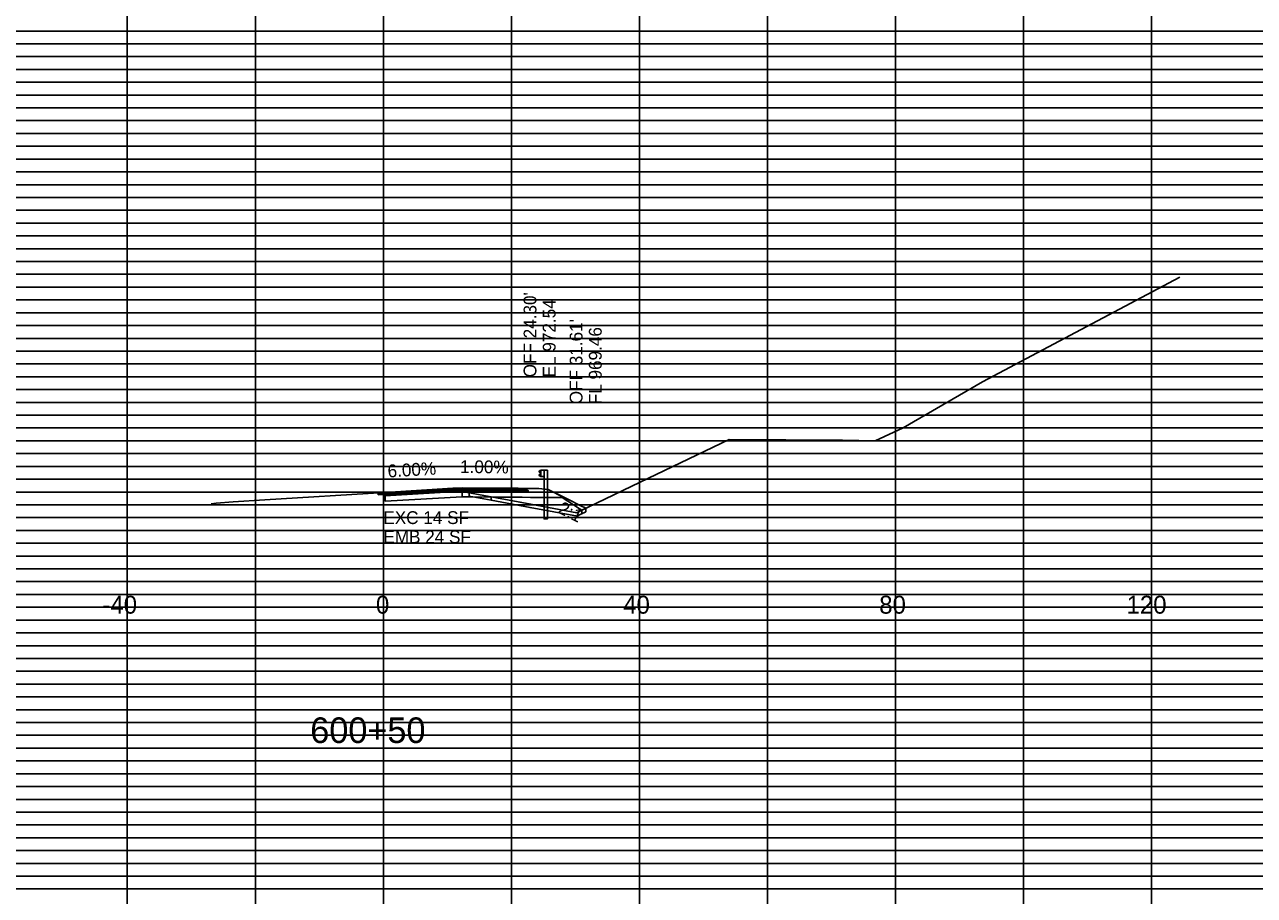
# Model space of a CAD drawing. Extents: x 2313580 to 2322968, y 282099 to 303247.
# Drawn here: x 2317145.2 to 2317337.4, y 287716.7 to 287852.7 of the extents above; entities that cross this region are included whole.
import ezdxf

# ---------------------------------------------------------------- set-up
doc = ezdxf.new("R2010")
doc.units = 0
for name, color, linetype in [('DESIGN - CENTERLINE - Proposed', 7, 'Continuous'), ('DESIGN - DRAINAGE - Text', 7, 'Continuous'), ('DESIGN - EARTHWORK - Excavation Limit Lines', 7, 'Continuous'), ('DESIGN - EARTHWORK - Shapes', 7, 'Continuous'), ('DESIGN - SCRATCH - User 5', 7, 'Continuous'), ('DESIGN - SHEET - Light Grid', 7, 'Continuous'), ('DESIGN - SHEET - Linework', 7, 'Continuous'), ('DESIGN - TYPICAL - Finished Grade and Subgrade', 7, 'Continuous'), ('DESIGN - TYPICAL - Finished Grade Slopes Text', 7, 'Continuous'), ('DESIGN - TYPICAL - Guardrail', 7, 'Continuous'), ('DESIGN - TYPICAL - Text', 7, 'Continuous'), ('Scratch Level', 7, 'Continuous'), ('SURVEY - GROUND - Top of Ground', 7, 'Continuous')]:
    doc.layers.add(name, color=color, linetype=linetype)

# ---------------------------------------------------------------- blocks, each defined once
blk = doc.blocks.new('GRTYP')
at = {"layer": 'DESIGN - CENTERLINE - Proposed'}
for p, q in [((0.162, 0.37), (0.162, 0.37)), ((0.162, 0.37), (0.162, 0.37)), ((0.264, 0.37), (0.264, 0.37)), ((0.264, 0.37), (0.264, 0.37))]:
    blk.add_line(p, q, dxfattribs=at)
for points in [[(0.059, 0.567), (0.04, 0.563), (0.004, 0.539), (0, 0.531), (0.004, 0.523), (0.055, 0.492), (0.059, 0.484), (0.059, 0.464), (0.055, 0.456), (0.004, 0.425), (0, 0.417), (0.004, 0.409), (0.04, 0.385), (0.059, 0.382)], [(0.162, 0.374), (0.059, 0.374), (0.059, 0.574), (0.162, 0.574)], [(0.264, -0.126), (0.264, 0.574), (0.162, 0.574), (0.162, -0.075)], [(0.162, -0.075), (0.162, -0.949), (0.264, -0.949), (0.264, -0.122)]]:
    blk.add_lwpolyline(points, dxfattribs=at)

msp = doc.modelspace()

# ---------------------------------------------------------------- linework, layer by layer
at = {"layer": 'DESIGN - EARTHWORK - Shapes'}
for points in [[(2317215.25, 287778.93), (2317214.68, 287779.03), (2317214.68, 287779.54), (2317213.6, 287779.74), (2317208.33, 287779.68), (2317201.47, 287779.61), (2317200.47, 287779.55), (2317200.47, 287779.45), (2317200.47, 287779.24), (2317201.58, 287779.3), (2317201.58, 287779.05), (2317201.58, 287778.22), (2317213.58, 287778.94)], [(2317218.13, 287778.9), (2317224.3, 287777.75), (2317231.5, 287776.44), (2317231.55, 287776.49), (2317231.79, 287776.6), (2317232.89, 287777.13), (2317232.05, 287777.55), (2317230.18, 287778.48), (2317229.58, 287778.78)]]:
    msp.add_lwpolyline(points, close=True, dxfattribs=at)
at = {"layer": 'DESIGN - SCRATCH - User 5'}
for points in [[(2317218.13, 287778.9), (2317214.68, 287779.54), (2317214.68, 287779.03), (2317218.13, 287778.39)], [(2317218.13, 287778.9), (2317214.68, 287779.54), (2317214.68, 287779.03), (2317218.13, 287778.39)], [(2317218.13, 287778.39), (2317224.21, 287777.25), (2317231.63, 287775.91), (2317231.82, 287776.06), (2317232.01, 287776.15), (2317232.28, 287776.28), (2317232.28, 287776.84), (2317231.79, 287776.6), (2317231.55, 287776.49), (2317231.5, 287776.44), (2317224.3, 287777.75), (2317218.13, 287778.9)], [(2317218.13, 287778.39), (2317224.21, 287777.25), (2317231.63, 287775.91), (2317231.82, 287776.06), (2317232.01, 287776.15), (2317232.89, 287776.58), (2317232.89, 287777.13), (2317231.79, 287776.6), (2317231.55, 287776.49), (2317231.5, 287776.44), (2317224.3, 287777.75), (2317218.13, 287778.9)]]:
    msp.add_lwpolyline(points, close=True, dxfattribs=at)
at = {"layer": 'DESIGN - SHEET - Light Grid'}
for p, q in [((2317041.28, 287851.67), (2317201.28, 287851.67)), ((2317201.28, 287851.67), (2317361.28, 287851.67)), ((2317041.28, 287849.67), (2317201.28, 287849.67)), ((2317201.28, 287849.67), (2317361.28, 287849.67)), ((2317041.28, 287845.67), (2317201.28, 287845.67)), ((2317201.28, 287845.67), (2317361.28, 287845.67)), ((2317041.28, 287843.67), (2317201.28, 287843.67)), ((2317201.28, 287843.67), (2317361.28, 287843.67)), ((2317041.28, 287841.67), (2317201.28, 287841.67)), ((2317201.28, 287841.67), (2317361.28, 287841.67)), ((2317041.28, 287839.67), (2317201.28, 287839.67)), ((2317201.28, 287839.67), (2317361.28, 287839.67)), ((2317041.28, 287837.67), (2317201.28, 287837.67)), ((2317201.28, 287837.67), (2317361.28, 287837.67)), ((2317041.28, 287835.67), (2317201.28, 287835.67)), ((2317201.28, 287835.67), (2317361.28, 287835.67)), ((2317041.28, 287833.67), (2317201.28, 287833.67)), ((2317201.28, 287833.67), (2317361.28, 287833.67)), ((2317041.28, 287831.67), (2317201.28, 287831.67)), ((2317201.28, 287831.67), (2317361.28, 287831.67)), ((2317041.28, 287829.67), (2317201.28, 287829.67)), ((2317201.28, 287829.67), (2317361.28, 287829.67)), ((2317041.28, 287825.67), (2317201.28, 287825.67)), ((2317201.28, 287825.67), (2317361.28, 287825.67)), ((2317041.28, 287823.67), (2317201.28, 287823.67)), ((2317201.28, 287823.67), (2317361.28, 287823.67)), ((2317041.28, 287821.67), (2317201.28, 287821.67)), ((2317201.28, 287821.67), (2317361.28, 287821.67)), ((2317041.28, 287819.67), (2317201.28, 287819.67)), ((2317201.28, 287819.67), (2317361.28, 287819.67)), ((2317041.28, 287817.67), (2317201.28, 287817.67)), ((2317201.28, 287817.67), (2317361.28, 287817.67)), ((2317041.28, 287815.67), (2317201.28, 287815.67)), ((2317201.28, 287815.67), (2317361.28, 287815.67)), ((2317041.28, 287813.67), (2317201.28, 287813.67)), ((2317201.28, 287813.67), (2317361.28, 287813.67)), ((2317041.28, 287811.67), (2317201.28, 287811.67)), ((2317201.28, 287811.67), (2317361.28, 287811.67)), ((2317041.28, 287809.67), (2317201.28, 287809.67)), ((2317201.28, 287809.67), (2317361.28, 287809.67)), ((2317041.28, 287805.67), (2317201.28, 287805.67)), ((2317201.28, 287805.67), (2317361.28, 287805.67)), ((2317041.28, 287803.67), (2317201.28, 287803.67)), ((2317201.28, 287803.67), (2317361.28, 287803.67)), ((2317041.28, 287801.67), (2317201.28, 287801.67)), ((2317201.28, 287801.67), (2317361.28, 287801.67)), ((2317041.28, 287799.67), (2317201.28, 287799.67)), ((2317201.28, 287799.67), (2317361.28, 287799.67)), ((2317041.28, 287797.67), (2317201.28, 287797.67)), ((2317201.28, 287797.67), (2317361.28, 287797.67)), ((2317041.28, 287795.67), (2317201.28, 287795.67)), ((2317201.28, 287795.67), (2317361.28, 287795.67)), ((2317041.28, 287793.67), (2317201.28, 287793.67)), ((2317201.28, 287793.67), (2317361.28, 287793.67)), ((2317041.28, 287791.67), (2317201.28, 287791.67)), ((2317201.28, 287791.67), (2317361.28, 287791.67)), ((2317041.28, 287789.67), (2317201.28, 287789.67)), ((2317201.28, 287789.67), (2317361.28, 287789.67)), ((2317041.28, 287785.67), (2317201.28, 287785.67)), ((2317201.28, 287785.67), (2317361.28, 287785.67)), ((2317041.28, 287783.67), (2317201.28, 287783.67)), ((2317201.28, 287783.67), (2317361.28, 287783.67)), ((2317041.28, 287781.67), (2317201.28, 287781.67)), ((2317201.28, 287781.67), (2317361.28, 287781.67)), ((2317041.28, 287779.67), (2317201.28, 287779.67)), ((2317201.28, 287779.67), (2317361.28, 287779.67)), ((2317041.28, 287777.67), (2317201.28, 287777.67)), ((2317201.28, 287777.67), (2317361.28, 287777.67)), ((2317041.28, 287775.67), (2317201.28, 287775.67)), ((2317201.28, 287775.67), (2317361.28, 287775.67)), ((2317041.28, 287773.67), (2317201.28, 287773.67)), ((2317201.28, 287773.67), (2317361.28, 287773.67)), ((2317041.28, 287771.67), (2317201.28, 287771.67)), ((2317201.28, 287771.67), (2317361.28, 287771.67)), ((2317041.28, 287769.67), (2317201.28, 287769.67)), ((2317201.28, 287769.67), (2317361.28, 287769.67)), ((2317041.28, 287765.67), (2317201.28, 287765.67)), ((2317201.28, 287765.67), (2317361.28, 287765.67)), ((2317041.28, 287763.67), (2317201.28, 287763.67)), ((2317201.28, 287763.67), (2317361.28, 287763.67)), ((2317041.28, 287761.67), (2317201.28, 287761.67)), ((2317201.28, 287761.67), (2317361.28, 287761.67)), ((2317041.28, 287759.67), (2317201.28, 287759.67)), ((2317201.28, 287759.67), (2317361.28, 287759.67)), ((2317041.28, 287757.67), (2317201.28, 287757.67)), ((2317201.28, 287757.67), (2317361.28, 287757.67)), ((2317041.28, 287755.67), (2317201.28, 287755.67)), ((2317201.28, 287755.67), (2317361.28, 287755.67)), ((2317041.28, 287753.67), (2317201.28, 287753.67)), ((2317201.28, 287753.67), (2317361.28, 287753.67)), ((2317041.28, 287751.67), (2317201.28, 287751.67)), ((2317201.28, 287751.67), (2317361.28, 287751.67)), ((2317041.28, 287749.67), (2317201.28, 287749.67)), ((2317201.28, 287749.67), (2317361.28, 287749.67)), ((2317041.28, 287745.67), (2317201.28, 287745.67)), ((2317201.28, 287745.67), (2317361.28, 287745.67)), ((2317041.28, 287743.67), (2317201.28, 287743.67)), ((2317201.28, 287743.67), (2317361.28, 287743.67)), ((2317041.28, 287741.67), (2317201.28, 287741.67)), ((2317201.28, 287741.67), (2317361.28, 287741.67)), ((2317041.28, 287739.67), (2317201.28, 287739.67)), ((2317201.28, 287739.67), (2317361.28, 287739.67)), ((2317041.28, 287737.67), (2317201.28, 287737.67)), ((2317201.28, 287737.67), (2317361.28, 287737.67)), ((2317041.28, 287735.67), (2317201.28, 287735.67)), ((2317201.28, 287735.67), (2317361.28, 287735.67)), ((2317041.28, 287733.67), (2317201.28, 287733.67)), ((2317201.28, 287733.67), (2317361.28, 287733.67)), ((2317041.28, 287731.67), (2317201.28, 287731.67)), ((2317201.28, 287731.67), (2317361.28, 287731.67)), ((2317041.28, 287729.67), (2317201.28, 287729.67)), ((2317201.28, 287729.67), (2317361.28, 287729.67)), ((2317041.28, 287725.67), (2317201.28, 287725.67)), ((2317201.28, 287725.67), (2317361.28, 287725.67)), ((2317041.28, 287723.67), (2317201.28, 287723.67)), ((2317201.28, 287723.67), (2317361.28, 287723.67)), ((2317041.28, 287721.67), (2317201.28, 287721.67)), ((2317201.28, 287721.67), (2317361.28, 287721.67)), ((2317041.28, 287719.67), (2317201.28, 287719.67)), ((2317201.28, 287719.67), (2317361.28, 287719.67)), ((2317041.28, 287717.67), (2317201.28, 287717.67)), ((2317201.28, 287717.67), (2317361.28, 287717.67))]:
    msp.add_line(p, q, dxfattribs=at)
at = {"layer": 'DESIGN - SHEET - Linework'}
for p, q in [((2317161.28, 287587.67), (2317161.28, 288007.67)), ((2317181.28, 287587.67), (2317181.28, 288007.67)), ((2317201.28, 287587.67), (2317201.28, 288007.67)), ((2317221.28, 287587.67), (2317221.28, 288007.67)), ((2317241.28, 287587.67), (2317241.28, 288007.67)), ((2317261.28, 287587.67), (2317261.28, 288007.67)), ((2317281.28, 287587.67), (2317281.28, 288007.67)), ((2317301.28, 287587.67), (2317301.28, 288007.67)), ((2317321.28, 287587.67), (2317321.28, 288007.67)), ((2316881.28, 287847.67), (2317521.28, 287847.67)), ((2316881.28, 287827.67), (2317521.28, 287827.67)), ((2316881.28, 287807.67), (2317521.28, 287807.67)), ((2316881.28, 287787.67), (2317521.28, 287787.67)), ((2316881.28, 287767.67), (2317521.28, 287767.67)), ((2316881.28, 287747.67), (2317521.28, 287747.67)), ((2316881.28, 287727.67), (2317521.28, 287727.67))]:
    msp.add_line(p, q, dxfattribs=at)
at = {"layer": 'DESIGN - TYPICAL - Finished Grade and Subgrade'}
msp.add_lwpolyline([(2317200.47, 287779.55), (2317201.45, 287779.61), (2317201.58, 287779.61), (2317212.13, 287780.25), (2317213.58, 287780.33), (2317222.36, 287780.25), (2317223.58, 287780.23), (2317225.58, 287780.21), (2317227.01, 287780.07), (2317228.96, 287779.1), (2317230.18, 287778.48), (2317232.05, 287777.55), (2317232.89, 287777.13)], dxfattribs=at)
for points in [[(2317201.58, 287779.61), (2317200.47, 287779.55), (2317200.47, 287779.45), (2317201.58, 287779.51)], [(2317201.58, 287779.61), (2317213.58, 287780.33), (2317213.58, 287780.23), (2317201.58, 287779.51)], [(2317201.58, 287779.51), (2317213.58, 287780.23), (2317213.58, 287780.03), (2317201.58, 287779.3)], [(2317201.58, 287779.3), (2317213.58, 287780.03), (2317213.58, 287779.78), (2317201.58, 287779.05)], [(2317201.58, 287779.05), (2317213.58, 287779.78), (2317213.58, 287778.94), (2317201.58, 287778.22)], [(2317213.58, 287780.33), (2317223.58, 287780.23), (2317223.58, 287780.13), (2317213.58, 287780.23)], [(2317213.58, 287780.23), (2317223.68, 287780.13), (2317223.68, 287779.93), (2317213.58, 287780.03)], [(2317213.58, 287779.78), (2317223.89, 287779.68), (2317223.89, 287779.93), (2317223.68, 287779.93), (2317223.68, 287780.13), (2317223.58, 287780.13), (2317223.58, 287780.23), (2317225.58, 287780.21), (2317227.01, 287780.07), (2317229.58, 287778.78), (2317213.58, 287778.94)], [(2317213.58, 287780.03), (2317223.89, 287779.93), (2317223.89, 287779.68), (2317213.58, 287779.78)], [(2317201.58, 287779.51), (2317201.58, 287779.3), (2317200.47, 287779.24), (2317200.47, 287779.45)]]:
    msp.add_lwpolyline(points, close=True, dxfattribs=at)
at = {"layer": 'Scratch Level'}
for points in [[(2317215.25, 287778.93), (2317214.68, 287779.03), (2317214.68, 287779.54), (2317213.6, 287779.74), (2317208.33, 287779.68), (2317201.47, 287779.61), (2317200.47, 287779.55), (2317200.47, 287779.45), (2317200.47, 287779.24), (2317201.58, 287779.3), (2317201.58, 287779.05), (2317201.58, 287778.22), (2317213.58, 287778.94)], [(2317218.13, 287778.9), (2317224.3, 287777.75), (2317231.5, 287776.44), (2317231.55, 287776.49), (2317231.79, 287776.6), (2317232.28, 287776.84), (2317231.88, 287777.09), (2317229.22, 287778.79), (2317229.22, 287778.79), (2317227.8, 287778.8)]]:
    msp.add_lwpolyline(points, close=True, dxfattribs=at)
at = {"layer": 'SURVEY - GROUND - Top of Ground'}
msp.add_lwpolyline([(2317174.36, 287777.85), (2317174.39, 287777.85), (2317175.14, 287777.91), (2317177.84, 287778.14), (2317182.78, 287778.45), (2317201.47, 287779.61), (2317208.33, 287779.68), (2317213.6, 287779.74), (2317224.3, 287777.75), (2317231.5, 287776.44), (2317231.55, 287776.49), (2317231.79, 287776.6), (2317240.11, 287780.6), (2317255.28, 287787.85), (2317273, 287787.76), (2317278.11, 287787.65), (2317282.49, 287789.69), (2317294.89, 287796.9), (2317325.71, 287813.21)], dxfattribs=at)

# ---------------------------------------------------------------- block references
at = {"layer": 'DESIGN - TYPICAL - Guardrail', "xscale": 5, "yscale": 5}
msp.add_blockref('GRTYP', (2317225.58, 287780.21), dxfattribs=at)

# ---------------------------------------------------------------- texts
at = {"layer": 'DESIGN - DRAINAGE - Text'}
for s, p in [("OFF 24.30'", (2317225.19, 287797.58)), ('EL 972.54', (2317228.19, 287797.58)), ("OFF 31.61'", (2317232.39, 287793.38)), ('FL 969.46', (2317235.39, 287793.38))]:
    msp.add_text(s, height=2, rotation=90, dxfattribs=at).set_placement(p)
at = {"layer": 'DESIGN - EARTHWORK - Excavation Limit Lines'}
for s, p in [('EXC 14 SF', (2317201.28, 287774.67)), ('EMB 24 SF', (2317201.28, 287771.67))]:
    msp.add_text(s, height=2, dxfattribs=at).set_placement(p)
at = {"layer": 'DESIGN - TYPICAL - Finished Grade Slopes Text'}
for s, rotation, p in [('6.00%', 3.4344, (2317202, 287781.94)), ('1.00%', 359.4279, (2317213.26, 287782.64)), ('2:1', 333.8029, (2317228.41, 287776.48))]:
    msp.add_text(s, height=2, rotation=rotation, dxfattribs=at).set_placement(p)
at = {"layer": 'DESIGN - TYPICAL - Text'}
for s, height, p in [('-40', 2.8, (2317157.39, 287760.67)), ('0', 2.8, (2317200.12, 287760.67)), ('40', 2.8, (2317238.75, 287760.67)), ('80', 2.8, (2317278.75, 287760.67)), ('120', 2.8, (2317317.39, 287760.67)), ('600+50', 4, (2317189.86, 287740.47))]:
    msp.add_text(s, height=height, dxfattribs=at).set_placement(p)

doc.saveas('drawing.dxf')
